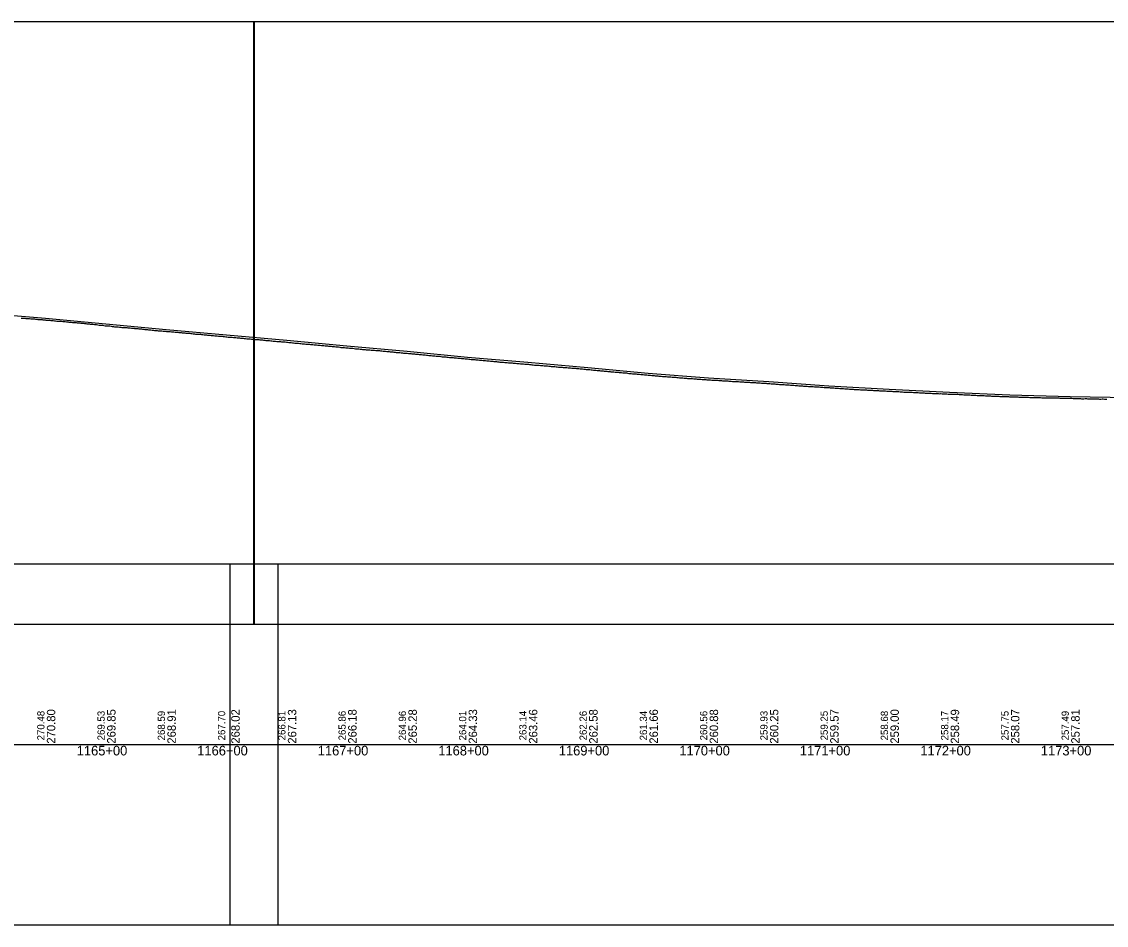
# Model space of a CAD drawing. Extents: x 2898 to 49495, y -15038 to -13538.
# Drawn here: x 5783 to 6683, y -15038 to -14288 of the extents above; entities that cross this region are included whole.
import ezdxf

# ---------------------------------------------------------------- set-up
doc = ezdxf.new("R2010")
doc.units = 0
for name, color, linetype in [('RD_DDB_Profile_EX', 7, 'Continuous'), ('RD_DDB_Profile_PR', 7, 'Continuous'), ('RD_DDB_StaTX', 7, 'Continuous'), ('RD_DDB_StripGrade', 7, 'Continuous'), ('RD_GPK_Profile_Cell', 7, 'Continuous'), ('RD_SHT_ShtClip', 7, 'Continuous')]:
    doc.layers.add(name, color=color, linetype=linetype)

msp = doc.modelspace()

# ---------------------------------------------------------------- linework, layer by layer
at = {"layer": 'RD_DDB_Profile_EX'}
for points in [[(5783.03, -14534.42), (5784.02, -14534.52), (5785.04, -14534.57), (5786.02, -14534.67), (5787.04, -14534.72), (5788.03, -14534.72), (5789.02, -14534.82), (5789.53, -14534.87), (5790.03, -14534.92), (5791.02, -14534.98), (5792.03, -14535.13), (5793.15, -14535.19), (5794.02, -14535.23), (5795.03, -14535.43), (5796.02, -14535.43), (5797.02, -14535.53), (5798.02, -14535.59), (5799.02, -14535.64), (5800.02, -14535.69), (5800.39, -14535.73), (5801.02, -14535.79), (5802.02, -14535.9), (5803.01, -14536.05), (5803.65, -14536.1), (5804.01, -14536.09), (5804.65, -14536.09), (5805.65, -14536.19), (5806.65, -14536.29), (5807.66, -14536.43), (5808.65, -14536.48), (5809.65, -14536.58), (5810.65, -14536.67), (5811.26, -14536.79), (5811.65, -14536.87), (5812.65, -14536.92), (5813.65, -14536.97), (5814.88, -14537.04), (5815.66, -14537.11), (5816.65, -14537.16), (5817.65, -14537.26), (5818.66, -14537.31), (5819.65, -14537.36), (5820.65, -14537.46), (5821.65, -14537.61), (5822.12, -14537.68), (5822.65, -14537.75), (5823.66, -14537.8), (5824.65, -14537.85), (5825.74, -14538.01), (5826.66, -14538.1), (5827.65, -14538.15), (5828.65, -14538.25), (5829.66, -14538.35), (5830.65, -14538.4), (5831.65, -14538.45), (5832.65, -14538.6), (5832.99, -14538.62), (5833.65, -14538.66), (5834.66, -14538.81), (5835.65, -14538.96), (5836.66, -14539.01), (5837.66, -14539.11), (5838.65, -14539.16), (5839.66, -14539.36), (5840.23, -14539.39), (5840.66, -14539.41), (5841.65, -14539.56), (5842.66, -14539.61), (5843.85, -14539.77), (5844.65, -14539.82), (5845.66, -14539.92), (5846.65, -14540.12), (5847.65, -14540.27), (5848.65, -14540.32), (5849.65, -14540.32), (5850.65, -14540.47), (5851.65, -14540.57), (5852.65, -14540.78), (5853.65, -14540.83), (5854.65, -14540.93), (5855.65, -14540.98), (5856.65, -14541.03), (5857.64, -14541.13), (5858.64, -14541.33)], [(5858.64, -14541.33), (5859.65, -14541.44), (5860.64, -14541.69), (5861.64, -14541.69), (5862.65, -14541.64), (5863.64, -14541.74), (5864.64, -14541.9), (5865.65, -14542.05), (5866.64, -14542.15), (5867.64, -14542.2), (5868.63, -14542.25), (5869.64, -14542.3), (5870.64, -14542.4), (5871.63, -14542.56), (5872.64, -14542.61), (5873.64, -14542.66), (5874.63, -14542.71), (5875.64, -14542.91), (5876.64, -14542.96), (5877.23, -14543.02), (5877.63, -14543.07), (5878.8, -14543.12), (5879.79, -14543.22), (5880.79, -14543.37), (5881.8, -14543.42), (5882.79, -14543.52), (5883.79, -14543.62), (5884.8, -14543.67), (5885.8, -14543.82), (5886.79, -14543.82), (5887.8, -14544.02), (5888.8, -14544.17), (5889.79, -14544.18), (5890.79, -14544.33), (5891.8, -14544.48), (5892.79, -14544.58), (5893.79, -14544.73), (5894.8, -14544.78), (5895.79, -14544.83), (5896.79, -14544.93), (5897.8, -14545.03), (5898.79, -14545.08), (5899.79, -14545.13), (5900.79, -14545.23), (5901.8, -14545.33), (5902.79, -14545.43), (5903.79, -14545.53), (5904.8, -14545.58), (5905.79, -14545.64), (5906.79, -14545.74), (5907.8, -14545.84), (5908.79, -14545.89), (5909.79, -14545.94), (5910.8, -14546.09), (5911.79, -14546.14), (5912.79, -14546.29), (5913.79, -14546.39), (5914.79, -14546.44), (5915.79, -14546.54), (5916.79, -14546.59), (5917.8, -14546.79), (5918.79, -14546.79), (5919.79, -14546.89), (5920.8, -14546.99), (5921.79, -14547.04), (5922.79, -14547.1), (5923.8, -14547.24), (5924.79, -14547.34), (5925.79, -14547.49), (5926.8, -14547.55), (5927.79, -14547.69), (5928.79, -14547.74), (5929.79, -14547.85), (5930.79, -14547.9), (5931.79, -14547.95), (5932.79, -14548.05), (5933.8, -14548.2), (5934.79, -14548.35), (5935.79, -14548.4), (5936.8, -14548.5), (5937.79, -14548.55), (5938.79, -14548.65), (5939.79, -14548.75), (5940.79, -14548.9), (5941.79, -14548.95), (5942.79, -14549), (5943.79, -14549.1), (5944.8, -14549.2), (5945.8, -14549.21), (5946.79, -14549.36), (5947.8, -14549.4), (5948.8, -14549.51), (5949.8, -14549.61), (5950.8, -14549.71), (5951.8, -14549.81), (5952.8, -14549.91), (5953.8, -14550.01), (5954.8, -14550.21), (5955.8, -14550.26), (5956.8, -14550.31), (5957.78, -14550.36)], [(5957.78, -14550.36), (5958.19, -14550.41), (5959.2, -14550.46), (5960.19, -14550.61), (5961.19, -14550.66), (5962.19, -14550.76), (5963.19, -14550.86), (5964.19, -14550.91), (5965.19, -14551.01), (5966.19, -14551.11), (5967.19, -14551.26), (5968.19, -14551.41), (5969.19, -14551.46), (5970.19, -14551.56), (5971.19, -14551.61), (5972.19, -14551.71), (5973.19, -14551.81), (5974.19, -14551.86), (5975.19, -14552.01), (5976.19, -14552.06), (5977.19, -14552.16), (5978.19, -14552.26), (5979.19, -14552.31), (5980.19, -14552.36), (5981.19, -14552.46), (5982.19, -14552.56), (5983.19, -14552.66), (5984.19, -14552.81), (5985.19, -14552.86), (5986.18, -14552.96), (5987.19, -14553.06), (5988.19, -14553.11), (5989.18, -14553.21), (5990.19, -14553.31), (5991.19, -14553.36), (5992.19, -14553.51), (5993.18, -14553.61), (5994.19, -14553.76), (5995.19, -14553.81), (5996.18, -14553.81), (5997.19, -14553.91), (5998.19, -14553.96), (5999.18, -14554.06), (6000.19, -14554.16), (6001.19, -14554.21), (6002.19, -14554.31), (6003.18, -14554.41), (6004.18, -14554.51), (6005.2, -14554.61), (6006.17, -14554.71), (6007.2, -14554.86), (6008.18, -14554.96), (6009.17, -14555.01), (6010.2, -14555.16), (6011.18, -14555.26), (6012.2, -14555.31), (6013.17, -14555.41), (6014.2, -14555.46), (6015.2, -14555.56), (6016.17, -14555.71), (6017.2, -14555.76), (6018.18, -14555.91), (6019.2, -14556.01), (6020.17, -14556.06), (6021.18, -14556.16), (6022.19, -14556.21), (6023.17, -14556.31), (6024.2, -14556.36), (6025.18, -14556.51), (6026.17, -14556.61), (6027.2, -14556.66), (6028.18, -14556.71), (6029.2, -14556.86), (6030.17, -14556.96), (6031.17, -14557.06), (6032.17, -14557.21), (6033.17, -14557.21), (6034.2, -14557.36), (6035.18, -14557.41), (6036.17, -14557.56), (6037.17, -14557.61), (6038.17, -14557.71), (6039.2, -14557.77), (6040.17, -14557.86), (6041.17, -14557.96), (6042.17, -14558.06), (6043.17, -14558.16), (6044.17, -14558.26), (6045.2, -14558.36), (6046.38, -14558.46), (6047.38, -14558.51), (6048.39, -14558.76), (6049.38, -14558.81), (6050.38, -14558.86), (6051.38, -14558.91), (6052.38, -14559.06), (6053.38, -14559.16), (6054.38, -14559.21), (6055.39, -14559.36), (6056.38, -14559.46), (6057.38, -14559.51)], [(6057.38, -14559.51), (6058.38, -14559.56), (6059.38, -14559.71), (6060.38, -14559.86), (6061.38, -14559.96), (6062.38, -14559.96), (6063.38, -14560.06), (6064.38, -14560.21), (6065.38, -14560.31), (6066.37, -14560.41), (6067.38, -14560.46), (6068.38, -14560.56), (6069.37, -14560.71), (6070.37, -14560.71), (6071.38, -14560.81), (6072.37, -14560.86), (6073.37, -14561.06), (6074.38, -14561.11), (6075.38, -14561.11), (6076.37, -14561.21), (6077.38, -14561.31), (6078.38, -14561.36), (6079.37, -14561.41), (6080.37, -14561.51), (6081.37, -14561.71), (6082.37, -14561.76), (6083.37, -14561.81), (6084.37, -14561.91), (6085.38, -14562.01), (6086.37, -14562.16), (6087.37, -14562.26), (6088.38, -14562.31), (6089.37, -14562.41), (6090.37, -14562.51), (6091.37, -14562.61), (6092.37, -14562.71), (6093.37, -14562.81), (6094.37, -14562.91), (6095.37, -14563.01), (6096.37, -14563.06), (6097.37, -14563.16), (6098.37, -14563.21), (6099.37, -14563.36), (6100.37, -14563.46), (6101.37, -14563.56), (6102.37, -14563.66), (6103.37, -14563.66), (6104.37, -14563.81), (6105.37, -14563.91), (6106.37, -14563.96), (6107.37, -14564.11), (6108.37, -14564.16), (6109.36, -14564.26), (6110.37, -14564.41), (6111.37, -14564.46), (6112.37, -14564.51), (6113.36, -14564.61), (6114.37, -14564.66), (6115.37, -14564.81), (6116.36, -14564.91), (6117.37, -14565.01), (6118.37, -14565.06), (6119.36, -14565.26), (6120.36, -14565.31), (6121.37, -14565.41), (6122.37, -14565.46), (6123.36, -14565.56), (6124.41, -14565.71), (6125.41, -14565.81), (6126.41, -14565.86), (6127.4, -14565.96), (6128.41, -14566.11), (6129.41, -14566.16), (6130.4, -14566.21), (6131.4, -14566.36), (6132.41, -14566.51), (6133.41, -14566.56), (6134.4, -14566.61), (6135.4, -14566.71), (6136.41, -14566.86), (6137.4, -14566.96), (6138.4, -14567.06), (6139.41, -14567.11), (6140.41, -14567.16), (6141.4, -14567.31), (6142.4, -14567.4), (6143.41, -14567.46), (6144.4, -14567.56), (6145.4, -14567.7), (6146.4, -14567.76), (6147.41, -14567.85), (6148.4, -14567.95), (6149.4, -14568.05), (6150.4, -14568.1), (6151.41, -14568.25), (6152.4, -14568.35), (6153.4, -14568.4), (6154.4, -14568.45), (6155.4, -14568.55), (6156.4, -14568.75), (6157.4, -14568.8)], [(6157.4, -14568.8), (6158.4, -14568.8), (6159.4, -14568.9), (6160.4, -14569), (6161.4, -14569.05), (6162.39, -14569.25), (6163.4, -14569.3), (6164.4, -14569.4), (6165.4, -14569.5), (6166.39, -14569.55), (6167.4, -14569.6), (6168.4, -14569.7), (6169.39, -14569.85), (6170.39, -14569.95), (6171.4, -14570.05), (6172.4, -14570.15), (6173.39, -14570.2), (6174.39, -14570.3), (6175.4, -14570.4), (6176.39, -14570.5), (6177.39, -14570.6), (6178.4, -14570.7), (6179.4, -14570.79), (6180.39, -14570.94), (6181.39, -14571.09), (6182.4, -14571.09), (6183.4, -14571.14), (6184.39, -14571.24), (6185.39, -14571.34), (6186.4, -14571.44), (6187.39, -14571.54), (6188.39, -14571.64), (6189.39, -14571.69), (6190.4, -14571.74), (6191.39, -14571.84), (6192.39, -14571.94), (6193.39, -14571.99), (6194.39, -14572.09), (6195.39, -14572.19), (6196.39, -14572.29), (6197.39, -14572.39), (6198.39, -14572.44), (6199.37, -14572.44), (6199.94, -14572.49), (6200.93, -14572.59), (6201.94, -14572.64), (6202.94, -14572.74), (6203.94, -14572.84), (6204.93, -14572.94), (6205.94, -14573.04), (6206.94, -14573.14), (6207.94, -14573.19), (6208.93, -14573.48), (6209.94, -14573.43), (6210.94, -14573.44), (6211.93, -14573.53), (6212.93, -14573.63), (6213.94, -14573.73), (6214.94, -14573.83), (6215.93, -14573.93), (6216.93, -14574.03), (6217.94, -14574.13), (6218.94, -14574.18), (6219.93, -14574.23), (6220.93, -14574.38), (6221.94, -14574.48), (6222.93, -14574.53), (6223.93, -14574.58), (6224.94, -14574.73), (6225.94, -14574.78), (6226.93, -14574.88), (6227.93, -14574.93), (6228.94, -14575.08), (6229.94, -14575.13), (6230.93, -14575.23), (6231.93, -14575.33), (6232.93, -14575.38), (6233.93, -14575.48), (6234.93, -14575.58), (6235.93, -14575.62), (6236.94, -14575.67), (6237.93, -14575.77), (6238.93, -14575.82), (6239.93, -14575.92), (6240.94, -14575.97), (6241.93, -14576.02), (6242.93, -14576.12), (6243.93, -14576.22), (6244.93, -14576.32), (6245.93, -14576.42), (6246.93, -14576.52), (6247.93, -14576.62), (6248.93, -14576.72), (6249.93, -14576.82), (6250.93, -14576.92), (6251.93, -14577.02), (6252.93, -14577.12), (6253.93, -14577.22), (6254.93, -14577.27), (6255.92, -14577.37), (6256.93, -14577.52)], [(6256.93, -14577.52), (6257.93, -14577.57), (6258.93, -14577.62), (6259.93, -14577.72), (6260.93, -14577.87), (6261.93, -14577.92), (6262.93, -14578.07), (6263.92, -14578.12), (6264.93, -14578.27), (6265.93, -14578.37), (6266.92, -14578.42), (6267.92, -14578.47), (6268.93, -14578.62), (6269.93, -14578.72), (6270.92, -14578.82), (6271.92, -14578.92), (6272.49, -14578.97), (6272.93, -14579.02), (6273.3, -14579.05), (6273.92, -14579.12), (6274.92, -14579.22), (6275.93, -14579.32), (6276.93, -14579.37), (6277.92, -14579.42), (6278.92, -14579.47), (6279.26, -14579.52), (6280.26, -14579.62), (6281.26, -14579.72), (6282.26, -14579.82), (6283.26, -14579.92), (6284.26, -14579.97), (6285.26, -14580.02), (6286.25, -14580.07), (6287.26, -14580.37), (6288.26, -14580.47), (6289.25, -14580.52), (6290.26, -14580.62), (6291.26, -14580.67), (6292.26, -14580.77), (6293.25, -14580.87), (6294.26, -14580.97), (6295.26, -14581.02), (6296.25, -14581.12), (6297.26, -14581.17), (6298.26, -14581.27), (6299.25, -14581.37), (6300.25, -14581.47), (6301.26, -14581.57), (6302.25, -14581.67), (6303.25, -14581.77), (6304.25, -14581.82), (6305.26, -14581.92), (6306.25, -14582.02), (6307.25, -14582.12), (6308.26, -14582.22), (6309.25, -14582.42), (6310.25, -14582.47), (6311.25, -14582.47), (6312.25, -14582.57), (6313.25, -14582.67), (6314.25, -14582.72), (6315.25, -14582.82), (6316.25, -14582.92), (6317.25, -14582.92), (6318.25, -14582.97), (6319.25, -14583.12), (6320.25, -14583.22), (6321.25, -14583.32), (6322.25, -14583.37), (6323.25, -14583.42), (6324.25, -14583.52), (6325.24, -14583.52), (6326.25, -14583.62), (6327.25, -14583.67), (6328.24, -14583.82), (6329.24, -14583.97), (6330.25, -14584.02), (6331.24, -14584.07), (6332.24, -14584.17), (6333.25, -14584.32), (6334.25, -14584.37), (6335.24, -14584.42), (6336.11, -14584.52), (6337.12, -14584.57), (6338.12, -14584.62), (6339.34, -14584.68), (6340.12, -14584.72), (6341.12, -14584.82), (6342.11, -14584.92), (6343.11, -14584.97), (6344.12, -14585.07), (6345.12, -14585.17), (6346.11, -14585.22), (6347.12, -14585.27), (6348.12, -14585.32), (6349.11, -14585.42), (6350.11, -14585.47), (6351.12, -14585.57), (6352.11, -14585.62), (6353.11, -14585.67), (6354.12, -14585.72)], [(6354.12, -14585.72), (6355.11, -14585.82), (6356.11, -14585.92), (6357.12, -14586.02), (6358.11, -14586.02), (6359.11, -14586.02), (6360.11, -14586.07), (6361.11, -14586.12), (6362.11, -14586.22), (6363.11, -14586.32), (6364.11, -14586.37), (6365.11, -14586.42), (6366.11, -14586.42), (6367.11, -14586.47), (6368.32, -14586.57), (6369.32, -14586.67), (6370.32, -14586.72), (6371.33, -14586.77), (6372.32, -14586.87), (6373.32, -14586.97), (6374.32, -14586.97), (6375.33, -14587.07), (6376.32, -14587.12), (6377.32, -14587.17), (6378.32, -14587.22), (6379.32, -14587.27), (6380.32, -14587.32), (6381.32, -14587.42), (6382.33, -14587.52), (6383.32, -14587.57), (6384.32, -14587.62), (6385.32, -14587.62), (6386.32, -14587.67), (6387.32, -14587.77), (6388.32, -14587.82), (6389.32, -14587.87), (6390.32, -14587.97), (6391.32, -14588.02), (6392.32, -14588.07), (6393.32, -14588.17), (6394.32, -14588.22), (6395.32, -14588.27), (6396.32, -14588.32), (6397.32, -14588.42), (6398.32, -14588.47), (6399.32, -14588.57), (6400.32, -14588.57), (6401.32, -14588.62), (6401.72, -14588.64), (6402.32, -14588.67), (6402.9, -14588.75), (6403.32, -14588.82), (6403.75, -14588.84), (6404.32, -14588.87), (6405.32, -14588.97), (6406.32, -14588.97), (6407.32, -14589.07), (6408.32, -14589.17), (6409.32, -14589.22), (6410.32, -14589.27), (6411.32, -14589.37), (6412.32, -14589.47), (6413.32, -14589.57), (6414.32, -14589.62), (6415.31, -14589.62), (6416.32, -14589.72), (6417.32, -14589.82), (6418.32, -14589.87), (6419.32, -14589.92), (6420.32, -14589.97), (6421.32, -14590.07), (6422.32, -14590.17), (6423.32, -14590.22), (6424.32, -14590.27), (6425.32, -14590.32), (6426.31, -14590.37), (6427.32, -14590.52), (6428.32, -14590.57), (6429.32, -14590.62), (6430.32, -14590.67), (6431.32, -14590.82), (6432.32, -14590.87), (6433.31, -14590.92), (6434.32, -14590.97), (6435.32, -14591.07), (6436.32, -14591.17), (6437.31, -14591.27), (6438.32, -14591.27), (6439.32, -14591.32), (6440.32, -14591.37), (6441.32, -14591.42), (6442.32, -14591.52), (6443.32, -14591.62), (6444.31, -14591.67), (6445.32, -14591.67), (6446.32, -14591.77), (6447.32, -14591.82), (6448.41, -14591.92), (6449.42, -14592.02), (6450.41, -14592.07), (6451.41, -14592.12)], [(6451.41, -14592.12), (6452.41, -14592.17), (6453.41, -14592.22), (6454.41, -14592.27), (6455.41, -14592.32), (6456.41, -14592.42), (6457.41, -14592.47), (6458.41, -14592.57), (6459.41, -14592.67), (6460.42, -14592.72), (6461.41, -14592.77), (6462.41, -14592.87), (6463.41, -14592.88), (6464.42, -14592.93), (6465.41, -14592.98), (6466.41, -14593.08), (6467.41, -14593.18), (6468.42, -14593.28), (6469.41, -14593.33), (6470.41, -14593.38), (6471.41, -14593.38), (6472.41, -14593.43), (6473.41, -14593.58), (6474.41, -14593.68), (6475.42, -14593.73), (6476.41, -14593.78), (6477.41, -14593.78), (6478.41, -14593.78), (6479.42, -14593.93), (6480.41, -14593.98), (6481.41, -14594.03), (6482.41, -14593.98), (6483.42, -14594.08), (6484.41, -14594.13), (6485.41, -14594.18), (6486.41, -14594.28), (6487.41, -14594.33), (6488.41, -14594.38), (6489.41, -14594.43), (6490.41, -14594.53), (6491.41, -14594.58), (6492.41, -14594.58), (6493.41, -14594.63), (6494.42, -14594.68), (6495.41, -14594.73), (6496.41, -14594.73), (6497.41, -14594.83), (6498.42, -14594.88), (6499.41, -14594.93), (6500.41, -14594.98), (6501.41, -14595.03), (6502.41, -14595.08), (6503.41, -14595.08), (6504.41, -14595.13), (6505.41, -14595.23), (6506.41, -14595.28), (6507.41, -14595.38), (6508.41, -14595.48), (6509.41, -14595.43), (6510.41, -14595.48), (6511.41, -14595.54), (6512.41, -14595.59), (6513.42, -14595.64), (6514.41, -14595.73), (6515.41, -14595.83), (6516.41, -14595.84), (6517.41, -14595.89), (6518.41, -14595.94), (6519.41, -14595.89), (6520.41, -14595.89), (6521.41, -14595.99), (6522.41, -14596.04), (6523.41, -14596.14), (6524.41, -14596.24), (6525.41, -14596.29), (6526.41, -14596.29), (6527.41, -14596.29), (6528.41, -14596.39), (6529.27, -14596.44), (6530.27, -14596.49), (6531.27, -14596.54), (6532.27, -14596.64), (6533.27, -14596.74), (6534.27, -14596.74), (6535.27, -14596.74), (6536.28, -14596.84), (6537.28, -14596.89), (6538.28, -14596.89), (6539.27, -14596.94), (6540.28, -14596.99), (6541.28, -14596.99), (6542.27, -14597.04), (6543.27, -14597.09), (6544.28, -14597.14), (6545.28, -14597.24), (6546.27, -14597.19), (6547.28, -14597.24), (6548.28, -14597.29), (6549.27, -14597.29), (6550.27, -14597.39), (6551.28, -14597.44)], [(6551.28, -14597.44), (6552.28, -14597.54), (6553.27, -14597.59), (6554.27, -14597.59), (6555.28, -14597.59), (6556.28, -14597.64), (6557.27, -14597.69), (6558.28, -14597.74), (6559.28, -14597.74), (6560.27, -14597.74), (6561.27, -14597.84), (6562.28, -14597.94), (6563.28, -14597.99), (6564.27, -14597.99), (6565.27, -14598.04), (6566.28, -14598.09), (6567.28, -14598.14), (6568.27, -14598.19), (6569.28, -14598.19), (6570.28, -14598.25), (6571.27, -14598.39), (6572.27, -14598.44), (6573.28, -14598.49), (6574.28, -14598.54), (6575.27, -14598.55), (6576.28, -14598.6), (6577.28, -14598.64), (6578.27, -14598.7), (6579.27, -14598.74), (6580.27, -14598.79), (6581.27, -14598.84), (6582.26, -14598.84), (6583.27, -14598.9), (6584.27, -14598.95), (6585.27, -14599), (6586.27, -14599.05), (6587.27, -14599.05), (6588.27, -14599.15), (6589.26, -14599.2), (6590.27, -14599.2), (6591.27, -14599.3), (6592.27, -14599.3), (6593.26, -14599.3), (6594.27, -14599.35), (6595.27, -14599.45), (6596.27, -14599.45), (6597.27, -14599.5), (6598.27, -14599.55), (6599.27, -14599.55), (6600.26, -14599.55), (6601.27, -14599.6), (6602.27, -14599.65), (6603.27, -14599.7), (6604.26, -14599.7), (6605.27, -14599.71), (6606.27, -14599.8), (6607.27, -14599.8), (6607.98, -14599.81), (6608.98, -14599.85), (6609.98, -14599.95), (6610.97, -14600), (6611.98, -14600), (6612.98, -14600), (6613.97, -14600.05), (6614.97, -14600.1), (6615.98, -14600.1), (6616.97, -14600.15), (6617.97, -14600.15), (6618.98, -14600.2), (6619.98, -14600.25), (6620.97, -14600.25), (6621.97, -14600.35), (6622.98, -14600.35), (6623.97, -14600.35), (6624.97, -14600.4), (6625.97, -14600.4), (6626.97, -14600.35), (6627.96, -14600.4), (6628.97, -14600.45), (6629.97, -14600.55), (6630.96, -14600.55), (6631.97, -14600.55), (6632.97, -14600.55), (6633.97, -14600.6), (6634.96, -14600.6), (6635.97, -14600.65), (6636.97, -14600.7), (6637.96, -14600.7), (6638.97, -14600.75), (6639.97, -14600.7), (6640.97, -14600.7), (6641.96, -14600.75), (6642.97, -14600.8), (6643.97, -14600.8), (6644.96, -14600.85), (6645.97, -14600.85), (6646.97, -14600.9), (6647.97, -14600.9), (6648.96, -14600.9), (6649.97, -14601), (6650.97, -14601.05)], [(6650.97, -14601.05), (6651.96, -14601.05), (6652.97, -14601), (6653.97, -14601.05), (6654.97, -14601.05), (6655.96, -14601.15), (6656.97, -14601.15), (6657.97, -14601.15), (6658.96, -14601.15), (6659.97, -14601.2), (6660.97, -14601.25), (6661.97, -14601.34), (6662.96, -14601.39), (6663.97, -14601.39), (6664.97, -14601.39), (6665.96, -14601.34), (6666.97, -14601.3), (6667.97, -14601.39), (6668.96, -14601.44), (6669.97, -14601.44), (6670.97, -14601.45), (6671.97, -14601.45), (6672.96, -14601.44), (6673.97, -14601.5), (6674.97, -14601.55), (6675.96, -14601.54), (6676.97, -14601.59), (6677.97, -14601.64), (6678.97, -14601.69), (6679.96, -14601.6), (6680.97, -14601.6), (6681.97, -14601.65), (6682.96, -14601.65), (6683.97, -14601.65)]]:
    msp.add_lwpolyline(points, dxfattribs=at)
at = {"layer": 'RD_DDB_Profile_PR'}
msp.add_lwpolyline([(5753.38, -14530.43), (5803.38, -14534.48), (5853.38, -14539.21), (5903.38, -14543.89), (5953.38, -14548.37), (6003.38, -14552.83), (6053.38, -14557.56), (6103.38, -14562.06), (6153.38, -14566.8), (6203.38, -14571.18), (6253.38, -14575.57), (6303.38, -14580.17), (6353.38, -14584.08), (6403.38, -14587.22), (6453.38, -14590.62), (6503.38, -14593.48), (6553.38, -14595.99), (6603.38, -14598.1), (6653.38, -14599.42), (6703.38, -14600.43)], dxfattribs=at)
at = {"layer": 'RD_GPK_Profile_Cell'}
msp.add_line((2976.05, -14888.47), (48721.13, -14888.47), dxfattribs=at)
at = {"layer": 'RD_SHT_ShtClip'}
for points in [[(5976.22, -14788.47), (5976.22, -14288.47), (5976.22, -14288.47), (4476.38, -14288.47), (4476.38, -14788.47)], [(7476.22, -14788.47), (7476.22, -14288.47), (7476.22, -14288.47), (5976.38, -14288.47), (5976.38, -14788.47)], [(4456.38, -14738.47), (5996.05, -14738.47), (5996.05, -15038.47), (4456.38, -15038.47)], [(5956.38, -14738.47), (7496.05, -14738.47), (7496.05, -15038.47), (5956.38, -15038.47)]]:
    msp.add_lwpolyline(points, close=True, dxfattribs=at)

# ---------------------------------------------------------------- texts
at = {"layer": 'RD_DDB_StaTX'}
for s, p in [('1165+00', (5829.18, -14897.47)), ('1166+00', (5929.18, -14897.47)), ('1167+00', (6029.18, -14897.47)), ('1168+00', (6129.18, -14897.47)), ('1169+00', (6229.18, -14897.47)), ('1170+00', (6329.18, -14897.47)), ('1171+00', (6429.18, -14897.47)), ('1172+00', (6529.18, -14897.47)), ('1173+00', (6629.18, -14897.47))]:
    msp.add_text(s, height=8, dxfattribs=at).set_placement(p)
at = {"layer": 'RD_DDB_StripGrade'}
for s, height, p in [('270.48', 6, (5802.38, -14884.98)), ('270.80', 7, (5811.38, -14887.72)), ('269.53', 6, (5852.38, -14884.98)), ('269.85', 7, (5861.38, -14887.72)), ('268.59', 6, (5902.38, -14884.98)), ('268.91', 7, (5911.38, -14887.72)), ('267.70', 6, (5952.38, -14884.98)), ('268.02', 7, (5964.42, -14887.72)), ('266.81', 6, (6002.38, -14884.98)), ('267.13', 7, (6011.38, -14887.72)), ('265.86', 6, (6052.38, -14884.98)), ('266.18', 7, (6061.38, -14887.72)), ('264.96', 6, (6102.38, -14884.98)), ('265.28', 7, (6111.38, -14887.72)), ('264.01', 6, (6152.38, -14884.98)), ('264.33', 7, (6161.38, -14887.72)), ('263.14', 6, (6202.38, -14884.98)), ('263.46', 7, (6211.38, -14887.72)), ('262.26', 6, (6252.38, -14884.98)), ('262.58', 7, (6261.38, -14887.72)), ('261.34', 6, (6302.38, -14884.98)), ('261.66', 7, (6311.38, -14887.72)), ('260.56', 6, (6352.38, -14884.98)), ('260.88', 7, (6361.38, -14887.72)), ('259.93', 6, (6402.38, -14884.98)), ('260.25', 7, (6411.38, -14887.72)), ('259.25', 6, (6452.38, -14884.98)), ('259.57', 7, (6461.38, -14887.72)), ('258.68', 6, (6502.38, -14884.98)), ('259.00', 7, (6511.38, -14887.72)), ('258.17', 6, (6552.38, -14884.98)), ('258.49', 7, (6561.38, -14887.72)), ('257.75', 6, (6602.38, -14884.98)), ('258.07', 7, (6611.38, -14887.72)), ('257.49', 6, (6652.38, -14884.98)), ('257.81', 7, (6661.38, -14887.72))]:
    msp.add_text(s, height=height, rotation=90, dxfattribs=at).set_placement(p)

doc.saveas('drawing.dxf')
